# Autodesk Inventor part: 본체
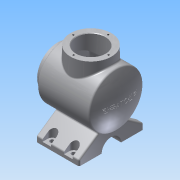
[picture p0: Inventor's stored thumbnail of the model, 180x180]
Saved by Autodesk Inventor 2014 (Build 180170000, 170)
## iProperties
Created: 2017-04
Part Number: 본체
Material: 알루미늄 6061
Document SubType Name: Modeling
Designer: SCD-A12
Density: 2.71 g/cm^3
Appearance: 알루미늄 - 평지
Mass: 1670.69 g
Surface Area: 1066.75 cm^2
Volume: 616.49 cm^3
Author: SCD-A12
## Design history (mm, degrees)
sketch "스케치1"
  geometry: L1 (12, 50)-(108.336, 50); L2 (0, 0)-(120, 0); L3 (0, 38)-(12, 38); L4 (12, 38)-(12, 50); L5 (0, 38)-(0, 0); L6 (0, 0)-(0, 27); L7 (0, 27)-(22, 27); L8 (22, 27)-(22, 37); L9 (25, 40)-(99.903, 40); L10 (120, 0)-(110, 0); L11 (62, 65)-(62, 0); L12 (62, 65)-(24, 65); L13 (24, 65)-(24, 0); L14 (66, 0)-(28, 0); L15 (35, 65)-(35, 0); L16 (39, 0)-(66, 0); L17 (24, 0)-(62, 0); L18 (35, 65)-(62, 65); L19 (62, 65)-(62, 0); L20 (62, 0)-(35, 0); L21 (35, 0)-(35, 65); L22 (120, 0)-(110, 0); A1 r 113 centre (7, 0) between (120, 0) and (108.336, 50); A2 r 3 centre (25, 37) between (25, 40) and (22, 37); A3 r 103 centre (7, 0) between (110, 0) and (102.69, 38.11); A4 r 3 centre (99.903, 37) between (102.69, 38.11) and (99.903, 40); 2 further points
  constraints: 44 end point, 10 perpendicular, 9 point on circle, 5 collinear, 5 point on line, 4 centre point, 4 tangent, 2 parallel
  dimensions: "d93" = 3 radius of A4; "d97" = 108 horizontal distance of L2.end L1.start
revolve "회전1" stored, may be unused: angle "d15" = 90 deg
revolve "회전2" stored, may be unused: angle "d18" = 90 deg
revolve "회전3" stored, may be unused: angle "d19" = 90 deg
revolve "회전4" stored, may be unused: angle "d20" = 90 deg
node "작업 평면1"
sketch "스케치2"
  geometry: L1 (18, -82)-(60, -82); L2 (60, -82)-(60, -72); L3 (60, -72)-(21.584, -45.101); L4 (-60, -82)-(-60, -72); L5 (-60, -72)-(-21.584, -45.101); L6 (-18, -82)-(-60, -82); A1 r 18 centre (0, -82) between (18, -82) and (-18, -82); A2 r 50 centre (0, 0) between (-21.584, -45.101) and (21.584, -45.101); 1 further point
  constraints: 12 end point, 4 point on circle, 2 centre point, 1 coincident, 1 perpendicular
  dimensions: "d85" = 55 deg angle of L2 L3; "d86" = 10 distance of L1.end L2.end; "d87" = 10 distance of L4.start L4.end; "d88" = 55 deg angle of L4 L5; "d89" = 42 distance of L6.start L4.start
extrude "돌출1" join sketch "스케치2" distance "d28" = 80; taper "d29" = 0 deg
node "작업 평면3"
sketch "스케치5"
  geometry: L1 (12, 110)-(12, 120); L2 (12, 120)-(28, 120); L3 (28, 120)-(28, 110); L4 (20, 110)-(20, 10); L5 (20, 10)-(20, 9); L6 (20, 9)-(20, 0); A1 r 8 centre (20, 110) between (12, 110) and (28, 110); 1 further point
  constraints: 12 end point, 2 collinear, 2 point on circle, 2 tangent, 1 centre point, 1 parallel, 1 perpendicular, 1 vertical
  dimensions: "d39" = 10 distance of L1.start L1.end; "d82" = 100 distance of L4.start L4.end; "d83" = 1 distance of L4.end L5.end; "d84" = 9 distance of L5.end L6.end
extrude "돌출2" cut sketch "스케치5" distance "d40" = 40; taper "d41" = 0 deg
hole "구멍1" sketch "스케치5" diameter "d42" = 8; stored, may be unused: countersink angle "d46" = 90 deg, drill point angle "d48" = 118 deg; dims "d43" = 6, "d44" = 4, "d45" = 2, "d47" = 8
sketch "스케치6" dims "d52" = 65
  geometry: L1 (0, 0)-(32.499, 0.269); C1 r 38 at (0, 0) reference; 2 further points
  constraints: 2 coincident, 2 end point, 6 other
hole "구멍2" sketch "스케치6" at (32.499, 0.269) diameter "d53" = 3.2; stored, may be unused: countersink angle "d57" = 90 deg, drill point angle "d59" = 118 deg; dims "d54" = 8, "d55" = 4, "d56" = 2, "d58" = 10
sketch "스케치7" dims "d63" = 65
  geometry: L1 (0, 0)-(32.5, 0); C1 r 38 at (0, 0) reference
  constraints: 2 end point, 1 coincident, 1 horizontal, 1 horizontal alignment, 2 other
hole "구멍3" sketch "스케치7" at (32.5, 0) diameter "d64" = 3.2; stored, may be unused: countersink angle "d68" = 90 deg, drill point angle "d70" = 118 deg; dims "d65" = 8, "d66" = 4, "d67" = 2, "d69" = 10
fillet "모깎기1" dims "d74" = 3
fillet "모깎기2" dims "d75" = 3
chamfer "모따기1" distance "d76" = 1; stored, may be unused: second distance "d77" = 2, angle "d78" = 45 deg
node "작업 평면4"
sketch "스케치8"
  geometry: 2 further points
  constraints: 1 coincident, 1 other
feature "엠보싱1" sketch "스케치8" dims "d80" = 0.5, "d81" = 0, "d93" = 3, "d97" = 108
node "솔리드1"
pattern_linear "직사각형 패턴1"
mirror "대칭1"
pattern_circular "원형 패턴1" dims angle "d61" = 360 deg
pattern_circular "원형 패턴3" dims angle "d95" = 360 deg
other parameters: "d21" = -8, "d35" = -6, "d79" = 160.5
